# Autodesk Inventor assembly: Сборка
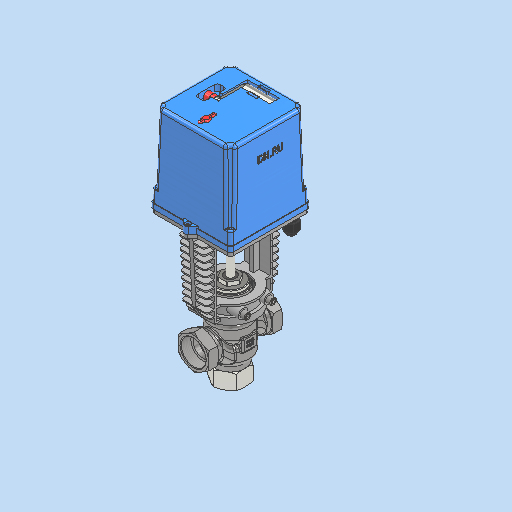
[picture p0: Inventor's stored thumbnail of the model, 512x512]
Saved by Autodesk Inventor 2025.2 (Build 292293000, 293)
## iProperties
Created: 2026-04
Part Number: Сборка
Document SubType Name: Assembly
Designer: igorr
Author: igorr
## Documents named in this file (7)
- D:\PROJECT CAD\DN.RU\...197(ACTUALE). VRg3M-S-31M-PED-T Клапан регулирующий трехходовой DN.ru\Исходники\DN32\Сборка.iam
- D:\PROJECT CAD\DN.RU\...197(ACTUALE). VRg3M-S-31M-PED-T Клапан регулирующий трехходовой DN.ru\Исходники\DN32\Деталь 1.ipt
- D:\PROJECT CAD\DN.RU\...197(ACTUALE). VRg3M-S-31M-PED-T Клапан регулирующий трехходовой DN.ru\Исходники\DN32\Деталь 2.ipt
- D:\PROJECT CAD\DN.RU\...197(ACTUALE). VRg3M-S-31M-PED-T Клапан регулирующий трехходовой DN.ru\Исходники\DN32\Деталь 3.ipt
- C:\Users\igorr\OneDrive\Документы\Inventor\Content Center Files\R2025\ru-RU\AS 1421(2)\AS 1421 - M10 x 12 засверленный конец.ipt
- C:\Users\igorr\OneDrive\Документы\Inventor\Content Center Files\R2025\ru-RU\AS 1420\AS 1420 - 1973 - M5 x 10.ipt
- C:\Users\igorr\OneDrive\Документы\Inventor\Content Center Files\R2025\ru-RU\AS 1427(05)\AS 1427 - M3 x 8(5) II.ipt
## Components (9 placed, 6 different names)
1. Деталь 1:1 — Касательность:1, Касательность:2, Угол:1, Совмещение:1, Совмещение:5, Угол:3, Совмещение:8, Совмещение:10, Совмещение:11
2. Деталь 2:1 — Касательность:1, Касательность:2, Угол:1, Совмещение:1
3. Деталь 3:1 — Совмещение:2, Совмещение:3, Угол:2, Совмещение:5, Угол:3, Совмещение:11
4. AS 1420 - метрическая M5 x 10:1 — Совмещение:8
5. AS 1420 - метрическая M5 x 10:2 — Совмещение:10
6. AS 1427 H - метрическая M3 x 8:1
7. AS 1427 H - метрическая M3 x 8:2
8. AS 1421 засверленный конец - метрическая M10 x 12 засверленный конец:1 — Заподлицо:1
9. AS 1421 засверленный конец - метрическая M10 x 12 засверленный конец:2 — Заподлицо:1
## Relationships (13: Mate 7, Angle 3, Tangent 2, Flush 1)
- Касательность:1 [Tangent]: Деталь 1:1 ↔ Деталь 2:1
- Касательность:2 [Tangent]: Деталь 1:1 ↔ Деталь 2:1
- Угол:1 [Angle]: Деталь 1:1 ↔ Деталь 2:1
- Совмещение:1 [Mate]: Деталь 1:1 ↔ Деталь 2:1
- Совмещение:2 [Mate]: Деталь 3:1
- Совмещение:3 [Mate]: Деталь 3:1
- Угол:2 [Angle]: Деталь 3:1
- Совмещение:5 [Mate]: Деталь 1:1 ↔ Деталь 3:1
- Угол:3 [Angle]: Деталь 1:1 ↔ Деталь 3:1
- Совмещение:8 [Mate]: Деталь 1:1 ↔ AS 1420 - метрическая M5 x 10:1
- Совмещение:10 [Mate]: Деталь 1:1 ↔ AS 1420 - метрическая M5 x 10:2
- Совмещение:11 [Mate]: Деталь 1:1 ↔ Деталь 3:1
- Заподлицо:1 [Flush]: AS 1421 засверленный конец - метрическая M10 x 12 засверленный конец:1 ↔ AS 1421 засверленный конец - метрическая M10 x 12 засверленный конец:2
